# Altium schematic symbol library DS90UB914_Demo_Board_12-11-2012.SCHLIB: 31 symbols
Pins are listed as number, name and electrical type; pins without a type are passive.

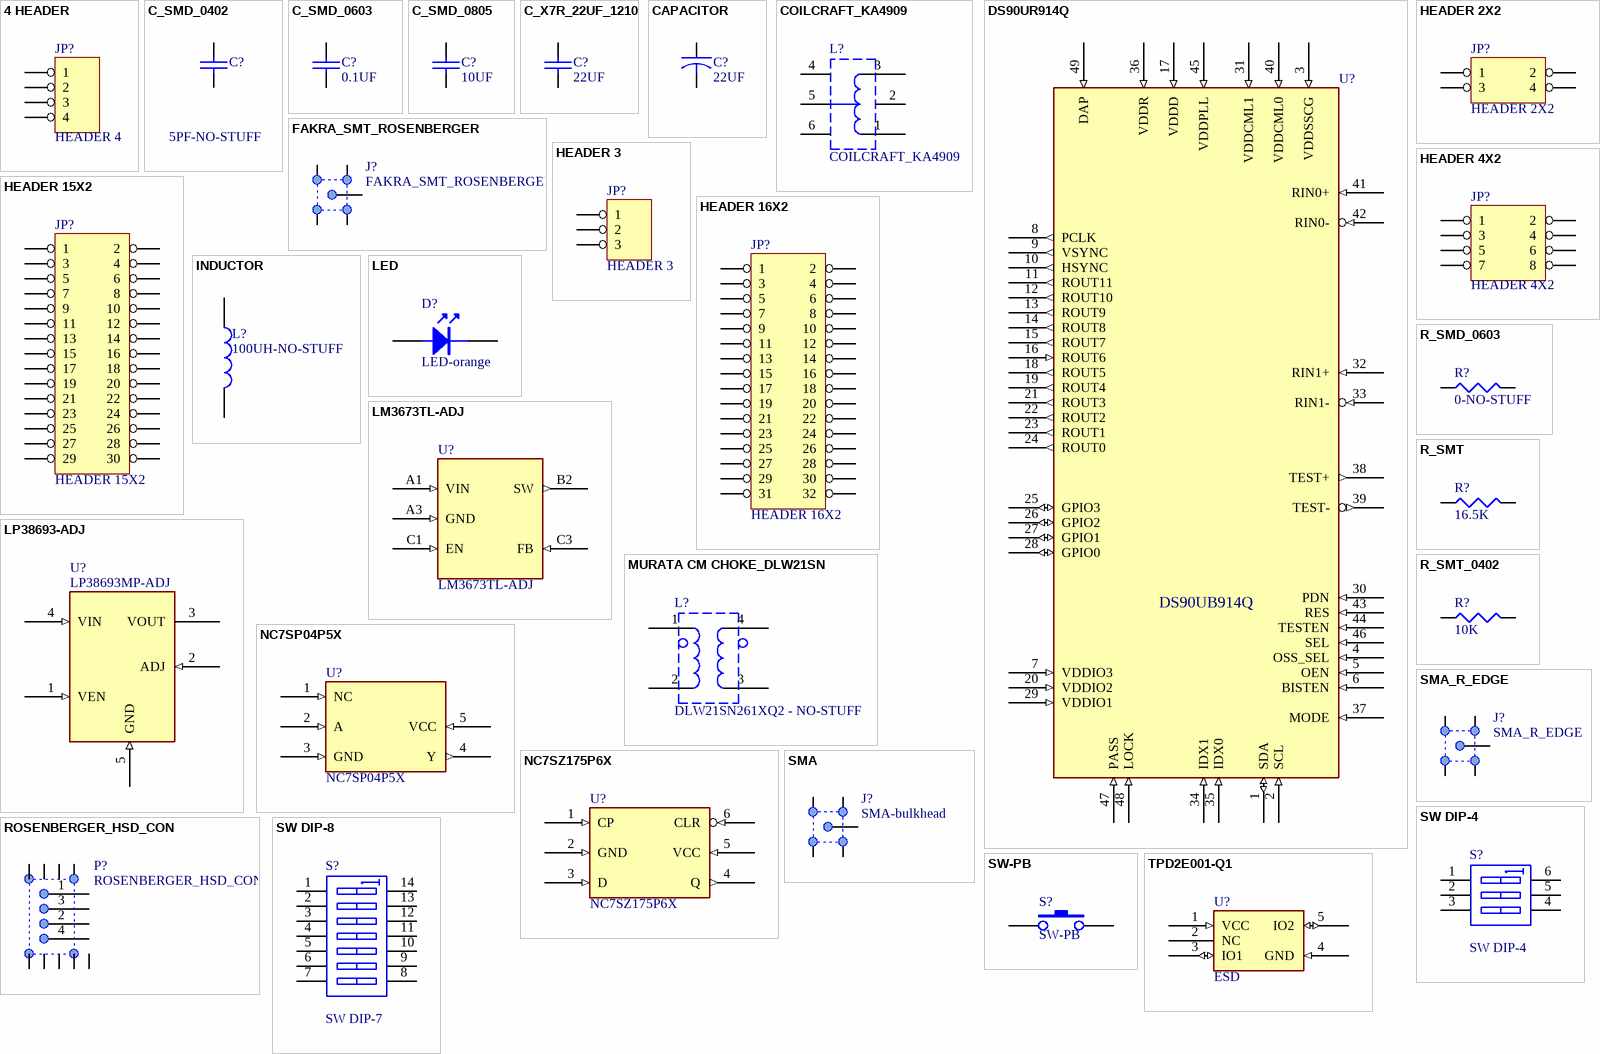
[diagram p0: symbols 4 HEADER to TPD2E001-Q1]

## 4 HEADER
designator JP?, comment HEADER 4
4 Pin Header
footprint HEADER 4x1
pins: 1, 2, 3, 4

## C_SMD_0402
designator C?, comment 5PF-NO-STUFF
Chip cap, X7R, 0402; Part Field 1: Murata GRM1555C1H5R0CZ01D, 5pF+-0.25pF, 50V, NPO, DigiKey# 490-1274-1-ND
footprint 0402
pins: 1, 2

## C_SMD_0603
designator C?, comment 0.1UF
Chip cap, X7R, +80/-20%, 50V, 0603; Part Field 1: Murata GRM188R72A104KA35D, 0.1UF, +-10%, 100V, X7R, DigiKey# 490-3285-1-ND
footprint 0603
pins: 1, 2

## C_SMD_0805
designator C?, comment 10UF
Chip cap, X7R, +80/-20%, 50V, 0805; Part Field 1: Murata GRM21BR61C106KE15L, 10UF, 10%, 16V, X5R, 0805, DigiKey# 490-3886-1-ND
footprint 0805
pins: 1, 2

## C_X7R_22UF_1210
designator C?, comment 22UF
Chip cap, X7R, 22UF, 16V, TDK, C3225X7R1C226K, DIGIKEY 445-3945-1-ND; Part Field 1: Murata GCM32ER71C226KE19L, 22UF, 10%, 16V, X7R, 1210, DigiKey# 490-5242-1-ND
footprint 1210
pins: 1, 2

## CAPACITOR
designator C?, comment 22UF
Capacitor
footprint 1210
pins: 1, 2

## COILCRAFT_KA4909
designator L?
COILCRAFT DIFF CHOKE KA4909-AL; Text Field1: Coilcraft differential choke KA4909-AL
pins: 1, 2, 3, 4, 5, 6

## DS90UR914Q
designator U?, comment DS90UB914Q
DS90UR914Q DESERIALIZER
footprint LLP48
pins: 1 SDA (io), 2 SCL (in), 3 VDDSSCG (in), 4 OSS_SEL (in), 5 OEN (in), 6 BISTEN (in), 7 VDDIO3 (in), 8 PCLK (out), 9 VSYNC (out), 10 HSYNC (out), 11 ROUT11 (out), 12 ROUT10 (out), 13 ROUT9 (out), 14 ROUT8 (out), 15 ROUT7 (out), 16 ROUT6 (in), 17 VDDD (in), 18 ROUT5 (out), 19 ROUT4 (out), 20 VDDIO2 (in), 21 ROUT3 (out), 22 ROUT2 (out), 23 ROUT1 (out), 24 ROUT0 (out), 25 GPIO3 (io), 26 GPIO2 (io), 27 GPIO1 (io), 28 GPIO0 (io), 29 VDDIO1 (in), 30 PDN (in), 31 VDDCML1 (in), 32 RIN1+ (in), 33 RIN1- (in), 34 IDX1 (in), 35 IDX0 (in), 36 VDDR (in), 37 MODE (in), 38 TEST+ (out), 39 TEST- (out), 40 VDDCML0 (in), 41 RIN0+ (in), 42 RIN0- (in), 43 RES (in), 44 TESTEN (in), 45 VDDPLL (in), 46 SEL (in), 47 PASS (in), 48 LOCK (in), 49 DAP (in)

## FAKRA_SMT_ROSENBERGER
designator J?
FAKRA connector, SMT, Rosenberger; Text Field1: Rosenberger FAKRA SMT connector, 59S20X-40ML5-Y
pins: 1 SIG, 2 SHIELD, 3 SHIELD, 4 SHIELD, 5 SHIELD

## HEADER 2X2
designator JP?
pins: 1, 2, 3, 4

## HEADER 3
designator JP?
pins: 1, 2, 3

## HEADER 4X2
designator JP?
pins: 1, 2, 3, 4, 5, 6, 7, 8

## HEADER 15X2
designator JP?
pins: 1, 2, 3, 4, 5, 6, 7, 8, 9, 10, 11, 12, 13, 14, 15, 16, 17, 18, 19, 20, 21, 22, 23, 24, 25, 26, 27, 28, 29, 30

## HEADER 16X2
designator JP?
pins: 1, 2, 3, 4, 5, 6, 7, 8, 9, 10, 11, 12, 13, 14, 15, 16, 17, 18, 19, 20, 21, 22, 23, 24, 25, 26, 27, 28, 29, 30, 31, 32

## INDUCTOR
designator L?, comment 100UH-NO-STUFF
pins: 1, 2

## LED
designator D?, comment LED-orange
footprint 0603
pins: A 1, K 2

## LM3673TL-ADJ
designator U?
LM3673TL-ADJ Step-Down DC-DC Converter; Part Field 1: LM3673TL-ADJ, DC-DC Down converter, DigiKey# LM3673TL-ADJCT-ND
footprint TLA05CBA
pins: A1 VIN (in), A3 GND (in), B2 SW (out), C1 EN (in), C3 FB (in)

## LP38693-ADJ
designator U?, comment LP38693MP-ADJ
LP38693MPADJ: 0.5A LDO REGULATOR, NSC; Part Field 1: LP38693MP-ADJ, LDO, SOT223-5, DigiKey#LP38693MP-ADJCT-ND
footprint SOT-223
pins: 1 VEN (in), 2 ADJ (in), 3 VOUT, 4 VIN (in), 5 GND (in)

## MURATA CM CHOKE_DLW21SN
designator L?, comment DLW21SN261XQ2 - NO-STUFF
Murata common mode choke, DLW21SN900HQ2, Digikey 490-5134-1-ND; Text Field1: Murata CM Choke
footprint Murata_DLW21
pins: 1, 2, 3, 4

## NC7SP04P5X
designator U?
NC7SP04P5X INVERTER; Part Field 1: Fairchild Semi, Inverter, NZ7SP04P5X, DigiKey# NC7SP04P5XCT-ND; Text Field1: Fairchild, NC7SP04 inverter, DigiKey #NC7SP04P5XCT-ND
footprint SC-70-5
footprint SC70-5
pins: 1 NC (in), 2 A (in), 3 GND (in), 4 Y (out), 5 VCC (in)

## NC7SZ175P6X
designator U?
NC7SZ175P6X LATCH; Part Field 1: Fairhild Semi, latch, NC7SZ175P6X, DigiKey# NC7SZ175P6XCT-ND
footprint SC70-6
pins: 1 CP (in), 2 GND (in), 3 D (in), 4 Q (out), 5 VCC (in), 6 CLR (in)

## R_SMD_0603
designator R?, comment 0-NO-STUFF
SMD R, +-1%, 0603; Part Field 1: Panasonic ERJ-3GEY0R00V, 0ohm, 0603, DigiKey# P0.0GCT-ND
footprint 0603
pins: 1, 2

## R_SMT
designator R?, comment 16.5K
Chip Resistor; Part Field 1: Panasonic ERJ-3EKF1652V, 1%, 100ppm, 0.1W, DigiKey P16.5KHCT-ND
footprint 0402
footprint 0603
footprint 0805
footprint 1206
pins: 1, 2

## R_SMT_0402
designator R?, comment 10K
SMT R, +-1%, 0402; Part Field 1: 10K+-5%, +-200ppm/C, Panasonic, ERJ-2GEJ103X, 0402, Digikey P10KJCT-ND
footprint 0402
pins: 1, 2

## ROSENBERGER_HSD_CON
designator P?
Rosenberger HSD connector, D4S20D-40ML5-Y
footprint ROSENBERGER_HSD_CON
pins: 1, 2, 3, 4, 5 SHIELD, 6 SHIELD, 7 SHIELD, 8 SHIELD, 9 SHIELD, 10 SHIELD, 11 SHIELD, 12 SHIELD, 13 SHIELD

## SMA
designator J?, comment SMA-bulkhead
SMA Connector; Part Field 1: Johnson end launch, bulkhead, round contact, 142-0701-871, digikey#  J610-ND
footprint sma-edge-tab
footprint sma-via-90deg
footprint sma-via
footprint sma-edge-round
pins: 1 SIG, 2 SHIELD, 3 SHIELD, 4 SHIELD, 5 SHIELD

## SMA_R_EDGE
designator J?
SMA Receptacle, edge lauch, Johnson; Text Field1: Johnson, 142-0701-851, tab contact, 62 mil board, gold plated
footprint sma-edge-tab
pins: 1 SIG, 2 SHIELD, 3 SHIELD, 4 SHIELD, 5 SHIELD

## SW DIP-4
designator S?
DIP Switch; Manufacturer: Grayhill Inc; Part_Number: 78B03ST
footprint 78B03ST (Footprint not found)
pins: 1 A1, 2 A2, 3 A3, 4 B3, 5 B2, 6 B1

## SW DIP-8
designator S?, comment SW DIP-7
DIP Switch
pins: 1 A1, 2 A2, 3 A3, 4 A4, 5 A5, 6 A6, 7 A7, 8 B7, 9 B6, 10 B5, 11 B4, 12 B3, 13 B2, 14 B1

## SW-PB
designator S?
pins: 1, 2

## TPD2E001-Q1
designator U?, comment ESD
TI TPD2E001Q1 2-CH ESD; Part Field 1: Digikey# 296-21883-1-ND
footprint SOT-533
pins: 1 VCC (in), 2 NC, 3 IO1 (io), 4 GND (in), 5 IO2 (io)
